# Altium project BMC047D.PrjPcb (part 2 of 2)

## Sheet BMC047D USB.SchDoc
size 431 x 279 mm; Date: Not shown in title block; ApprovedBy: Not shown in title block; CheckedBy: Not shown in title block; Author: Not shown in title block; CompanyName: Not shown in title block; Engineer: Not shown in title block; Organization: Not shown in title block; Address1: Not shown in title block; Address2: Not shown in title block; Address3: Not shown in title block; Address4: Not shown in title block; DocumentNumber: 2; Revision: Use project parameter SCH_Rev; SheetNumber: 2; SheetTotal: 3; PageSetup: Record=PageOptions¦CenterHorizontal=True¦CenterVertical=True¦PrintScale=0.96¦XCorrection=1.00¦YCorrection=1.00¦PrintKind=0¦BorderSize=5000000¦LeftOffset=0¦BottomOffset=0¦Orientation=2¦PaperLength=1000¦PaperWidth=1000¦Scale=100¦PaperSource=15¦PrintQuality=-3¦MediaType=1¦DitherType=10¦PrintScaleMode=1¦PaperKind=Tabloid (11 x 17")¦PaperIndex=17
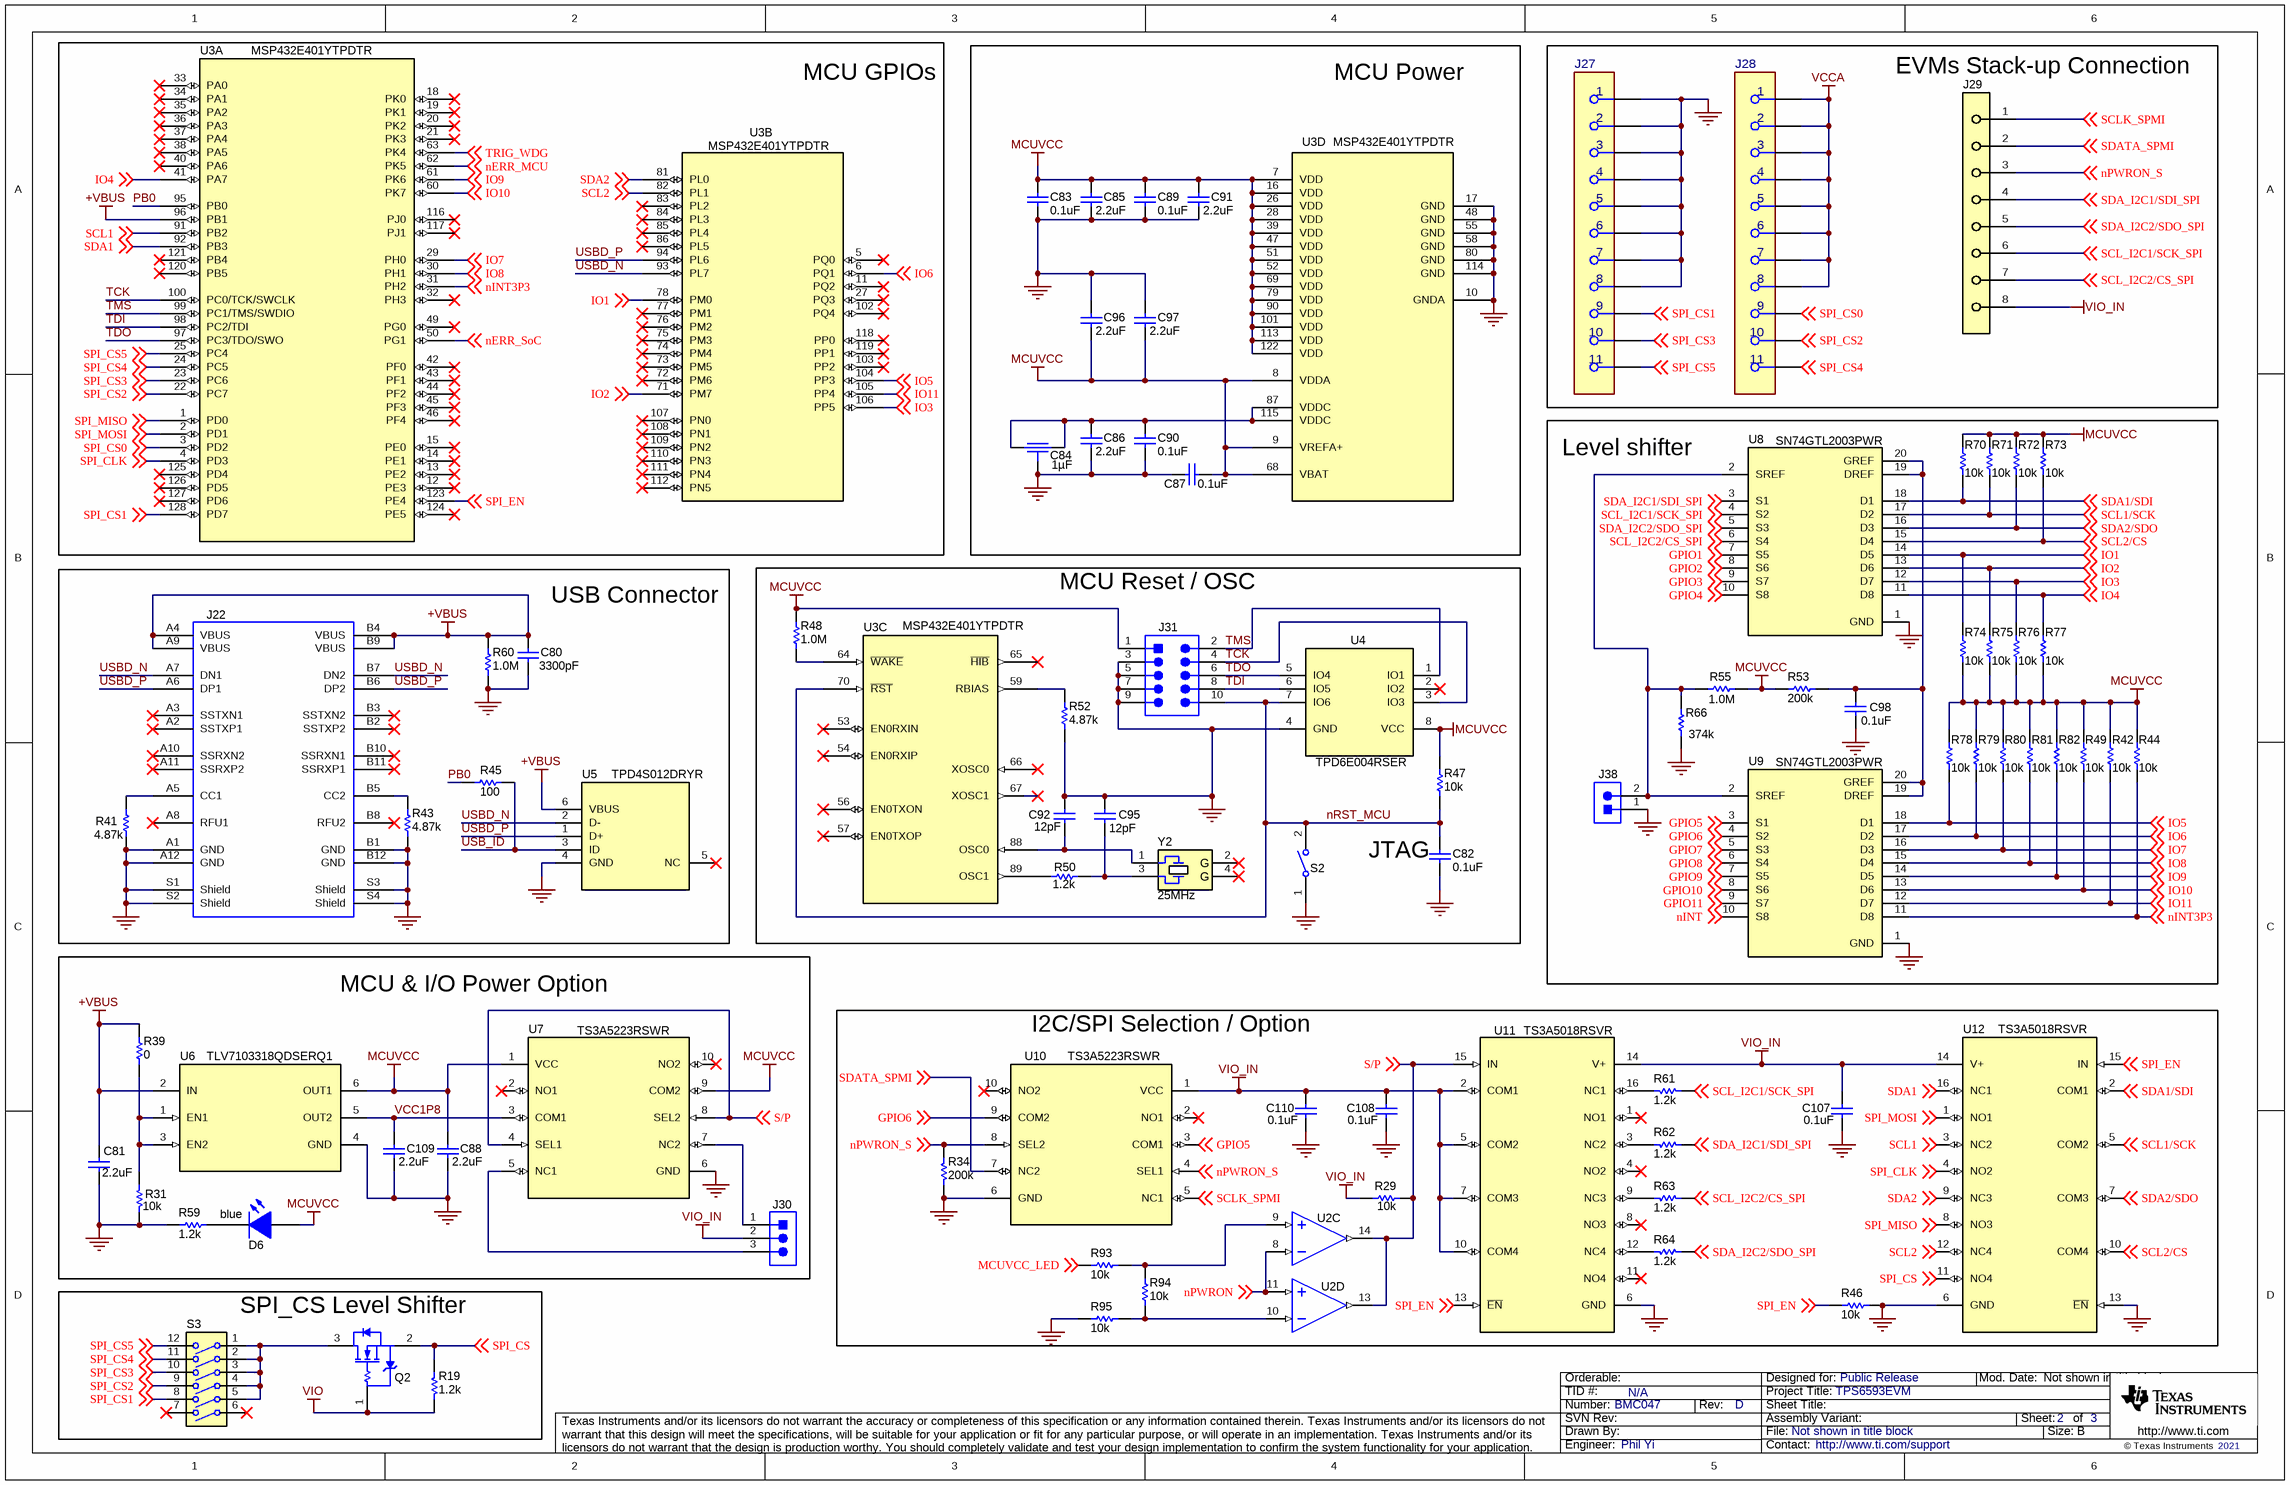
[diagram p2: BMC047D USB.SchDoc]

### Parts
C80  ValueDisplayed: 3300pF  [0603L]  (hidden comment: C0603C332K5RACTU)
C81  ValueDisplayed: 2.2uF  [0603L]  (hidden comment: CGA3E1X7S1C225M080AC)
C82  ValueDisplayed: 0.1uF  [0402L]  (hidden comment: GCM155R71C104KA55D)
C83  ValueDisplayed: 0.1uF  [0402L]  (hidden comment: GCM155R71C104KA55D)
C84  ValueDisplayed: 1µF  [FP-NFM15HC105D0G3_0402-MFG]  (hidden comment: NFM15HC105D0G3)
C85  ValueDisplayed: 2.2uF  [0603L]  (hidden comment: CGA3E1X7S1C225M080AC)
C86  ValueDisplayed: 2.2uF  [0603L]  (hidden comment: CGA3E1X7S1C225M080AC)
C87  ValueDisplayed: 0.1uF  [0402L]  (hidden comment: GCM155R71C104KA55D)
C88  ValueDisplayed: 2.2uF  [0603L]  (hidden comment: CGA3E1X7S1C225M080AC)
C89  ValueDisplayed: 0.1uF  [0402L]  (hidden comment: GCM155R71C104KA55D)
C90  ValueDisplayed: 0.1uF  [0402L]  (hidden comment: GCM155R71C104KA55D)
C91  ValueDisplayed: 2.2uF  [0603L]  (hidden comment: CGA3E1X7S1C225M080AC)
C92  ValueDisplayed: 12pF  [0402L]  (hidden comment: GCM1555C1H120JA16J)
C95  ValueDisplayed: 12pF  [0402L]  (hidden comment: GCM1555C1H120JA16J)
C96  ValueDisplayed: 2.2uF  [0603L]  (hidden comment: CGA3E1X7S1C225M080AC)
C97  ValueDisplayed: 2.2uF  [0603L]  (hidden comment: CGA3E1X7S1C225M080AC)
C98  value 0.1uF  [0402L]  (hidden comment: GCM155R71C104KA55D)
C107  ValueDisplayed: 0.1uF  [0402L]  (hidden comment: GCM155R71C104KA55D)
C108  ValueDisplayed: 0.1uF  [0402L]  (hidden comment: GCM155R71C104KA55D)
C109  ValueDisplayed: 2.2uF  [0603L]  (hidden comment: CGA3E1X7S1C225M080AC)
C110  ValueDisplayed: 0.1uF  [0402L]  (hidden comment: GCM155R71C104KA55D)
D6  Color: blue  [LB Q39G_BLUE]  (hidden comment: LB Q39G-L2N2-35-1)
J22  12401610E4#2A  [Amphenol_12401610E4_2A]  (value not drawn)
J27  ESQ-111-14-T-S  [FP-ESQ-111-14-T-S_HDR11-MFG]  (value not drawn)
J28  ESQ-111-14-T-S  [FP-ESQ-111-14-T-S_HDR11-MFG]  (value not drawn)
J29  ESQ-108-14-T-S  [FP-ESQ-108-14-T-S_HDR8-MFG]  (value not drawn)
J30  61300311121  [WURTH_61300311121]  (value not drawn)
J31  SH-105-01-F-DV-K  [Samtec_FTSH-105-01-x-DV-K]  (value not drawn)
J38  TSW-102-23-T-S  [Samtec_TSW-102-23-X-S]  (value not drawn)
Q2  CSD13381F4  [YJC0003A]  (value not drawn)
R19  ValueDisplayed: 1.2k  [0402L]  (hidden comment: CRCW04021K20JNED)
R29  ValueDisplayed: 10k  [0402L]  (hidden comment: CRCW040210K0JNED)
R31  ValueDisplayed: 10k  [0402L]  (hidden comment: CRCW040210K0JNED)
R34  ValueDisplayed: 200k  [0402]  (hidden comment: CRCW0402200KJNED)
R39  ValueDisplayed: 0  [0402L]  (hidden comment: RK73Z1ETTP)
R41  ValueDisplayed: 4.87k  [0402L]  (hidden comment: CRCW04024K87FKED)
R42  ValueDisplayed: 10k  [0402L]  (hidden comment: CRCW040210K0JNED)
R43  ValueDisplayed: 4.87k  [0402L]  (hidden comment: CRCW04024K87FKED)
R44  ValueDisplayed: 10k  [0402L]  (hidden comment: CRCW040210K0JNED)
R45  ValueDisplayed: 100  [0402L]  (hidden comment: CRCW0402100RJNED)
R46  ValueDisplayed: 10k  [0402L]  (hidden comment: CRCW040210K0JNED)
R47  ValueDisplayed: 10k  [0402L]  (hidden comment: CRCW040210K0JNED)
R48  ValueDisplayed: 1.0M  [0402L]  (hidden comment: CRCW04021M00JNED)
R49  ValueDisplayed: 10k  [0402L]  (hidden comment: CRCW040210K0JNED)
R50  ValueDisplayed: 1.2k  [0402L]  (hidden comment: CRCW04021K20JNED)
R52  ValueDisplayed: 4.87k  [0402L]  (hidden comment: CRCW04024K87FKED)
R53  ValueDisplayed: 200k  [0402L]  (hidden comment: CRCW0402200KJNED)
R55  ValueDisplayed: 1.0M  [0402L]  (hidden comment: CRCW04021M00JNED)
R59  ValueDisplayed: 1.2k  [0402L]  (hidden comment: CRCW04021K20JNED)
R60  ValueDisplayed: 1.0M  [0402L]  (hidden comment: CRCW04021M00JNED)
R61  ValueDisplayed: 1.2k  [0402L]  (hidden comment: CRCW04021K20JNED)
R62  ValueDisplayed: 1.2k  [0402L]  (hidden comment: CRCW04021K20JNED)
R63  ValueDisplayed: 1.2k  [0402L]  (hidden comment: CRCW04021K20JNED)
R64  ValueDisplayed: 1.2k  [0402L]  (hidden comment: CRCW04021K20JNED)
R66  ValueDisplayed: 374k  [0402L]  (hidden comment: CRCW0402374KFKED)
R70  ValueDisplayed: 10k  [0402L]  (hidden comment: CRCW040210K0JNED)
R71  ValueDisplayed: 10k  [0402L]  (hidden comment: CRCW040210K0JNED)
R72  ValueDisplayed: 10k  [0402L]  (hidden comment: CRCW040210K0JNED)
R73  ValueDisplayed: 10k  [0402L]  (hidden comment: CRCW040210K0JNED)
R74  ValueDisplayed: 10k  [0402L]  (hidden comment: CRCW040210K0JNED)
R75  ValueDisplayed: 10k  [0402L]  (hidden comment: CRCW040210K0JNED)
R76  ValueDisplayed: 10k  [0402L]  (hidden comment: CRCW040210K0JNED)
R77  ValueDisplayed: 10k  [0402L]  (hidden comment: CRCW040210K0JNED)
R78  ValueDisplayed: 10k  [0402L]  (hidden comment: CRCW040210K0JNED)
R79  ValueDisplayed: 10k  [0402L]  (hidden comment: CRCW040210K0JNED)
R80  ValueDisplayed: 10k  [0402L]  (hidden comment: CRCW040210K0JNED)
R81  ValueDisplayed: 10k  [0402L]  (hidden comment: CRCW040210K0JNED)
R82  ValueDisplayed: 10k  [0402L]  (hidden comment: CRCW040210K0JNED)
R93  ValueDisplayed: 10k  [0402L]  (hidden comment: CRCW040210K0JNED)
R94  ValueDisplayed: 10k  [0402L]  (hidden comment: CRCW040210K0JNED)
R95  ValueDisplayed: 10k  [0402L]  (hidden comment: CRCW040210K0JNED)
S2  147873-1  [SW_147873-1]  (value not drawn)
S3  218-6LPST  [SW_218-6LPST]  (value not drawn)
U2  LM2901AVQPWRQ1  [PW0014A_N]  (value not drawn)  (parts C,D of 5)
U3  MSP432E401YTPDTR  [PDT0128A]  (parts A,B,C,D of 4)
U4  TPD6E004RSER  [RSE0008A]
U5  TPD4S012DRYR  [DRY0006A]
U6  TLV7103318QDSERQ1  [DSE0006A]
U7  TS3A5223RSWR  [RSW0010A]
U8  SN74GTL2003PWR  [PW0020A_N]
U9  SN74GTL2003PWR  [PW0020A_N]
U10  TS3A5223RSWR  [RSW0010A]
U11  TS3A5018RSVR  [RSV0016A]
U12  TS3A5018RSVR  [RSV0016A]
Y2  Frequency_Fixed: 25MHz  [NDK_NX3225GA]  (hidden comment: NX3225GA-25.000M-STD-CRG-2)

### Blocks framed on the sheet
MCU GPIOs: U3
MCU Power: C83-C87 C89-C91 C96 C97 U3
EVMs Stack-up Connection: J27-J29
Level shifter: C98 J38 R42 R44 R49 R53 R55 R66 R70-R82 U8 U9
USB Connector: C80 J22 R41 R43 R45 R60 U5
MCU & I/O Power Option: C81 C88 C109 D6 J30 R31 R39 R59 U6 U7
I2C/SPI Selection / Option: C107 C108 C110 R29 R34 R46 R61-R64 R93-R95 U2 U10-U12
SPI_CS Level Shifter: Q2 R19 S3

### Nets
+VBUS: C80.1 C81.1 J22.A4(VBUS) J22.A9(VBUS) J22.B4(VBUS) J22.B9(VBUS) R39.1 R60.1 U3.96(PB1) U5.6(VBUS) U6.2(IN)
GND: C80.2 C81.2 C82.2 C83.2 C84.2 C85.2 C86.2 C87.1 C88.2 C89.2 C90.2 C91.2 C92.2 C95.2 C96.1 C97.1 C98.2 C107.1 C108.1 C109.2 C110.1 J22.A1(GND) J22.A12(GND) J22.B1(GND) J22.B12(GND) J22.S1(Shield) J22.S2(Shield) J22.S3(Shield) J22.S4(Shield) J27.1 J27.2 J27.3 J27.4 J27.5 J27.6 J27.7 J27.8 J31.3 J31.5 J31.7 J31.9 J38.1 R31.1 R34.1 R41.2 R43.2 R46.1 R52.2 R59.2 R60.2 R66.1 R95.2 S2.1 U3.10(GNDA) U3.17(GND) U3.48(GND) U3.55(GND) U3.58(GND) U3.80(GND) U3.114(GND) U4.4(GND) U5.4(GND) U6.4(GND) U7.6(GND) U8.1(GND) U9.1(GND) U10.6(GND) U11.6(GND) U12.6(GND) U12.13(~{EN})
MCUVCC: C83.1 C85.1 C87.2 C88.1 C89.1 C91.1 C96.2 C97.2 D6.1(A) J31.1 R42.1 R44.1 R47.2 R48.2 R49.1 R53.1 R55.2 R70.1 R71.1 R72.1 R73.1 R74.2 R75.2 R76.2 R77.2 R78.1 R79.1 R80.1 R81.1 R82.1 U3.7(VDD) U3.8(VDDA) U3.9(VREFA+) U3.16(VDD) U3.26(VDD) U3.28(VDD) U3.39(VDD) U3.47(VDD) U3.51(VDD) U3.52(VDD) U3.68(VBAT) U3.69(VDD) U3.79(VDD) U3.90(VDD) U3.101(VDD) U3.113(VDD) U3.122(VDD) U4.8(VCC) U6.6(OUT1) U7.1(VCC) U7.9(COM2)
VCCA: J28.1 J28.2 J28.3 J28.4 J28.5 J28.6 J28.7 J28.8
VIO: Q2.1(G) R19.1
VIO_IN: C107.2 C108.2 C110.2 J29.8 J30.2 R29.1 U10.1(VCC) U11.2(COM1) U11.5(COM2) U11.7(COM3) U11.10(COM4) U11.14(V+) U12.14(V+)
GPIO1: U8.7(S5) ; off-sheet GPIO1
GPIO2: U8.8(S6) ; off-sheet GPIO2
GPIO3: U8.9(S7) ; off-sheet GPIO3
GPIO4: U8.10(S8) ; off-sheet GPIO4
GPIO5: U9.3(S1) U10.3(COM1) ; off-sheet GPIO5
GPIO6: U9.4(S2) U10.9(COM2) ; off-sheet GPIO6
GPIO7: U9.5(S3) ; off-sheet GPIO7
GPIO8: U9.6(S4) ; off-sheet GPIO8
GPIO9: U9.7(S5) ; off-sheet GPIO9
GPIO10: U9.8(S6) ; off-sheet GPIO10
GPIO11: U9.9(S7) ; off-sheet GPIO11
IO1: R74.1 U3.78(PM0) U8.14(D5) ; off-sheet IO1
IO2: R75.1 U3.71(PM7) U8.13(D6) ; off-sheet IO2
IO3: R76.1 U3.106(PP5) U8.12(D7) ; off-sheet IO3
IO4: R77.1 U3.41(PA7) U8.11(D8) ; off-sheet IO4
IO5: R78.2 U3.104(PP3) U9.18(D1) ; off-sheet IO5
IO6: R79.2 U3.6(PQ1) U9.17(D2) ; off-sheet IO6
IO7: R80.2 U3.29(PH0) U9.16(D3) ; off-sheet IO7
IO8: R81.2 U3.30(PH1) U9.15(D4) ; off-sheet IO8
IO9: R82.2 U3.61(PK6) U9.14(D5) ; off-sheet IO9
IO10: R49.2 U3.60(PK7) U9.13(D6) ; off-sheet IO10
IO11: R42.2 U3.105(PP4) U9.12(D7) ; off-sheet IO11
MCUVCC_LED: R93.1 ; off-sheet MCUVCC_LED
nERR_MCU: U3.62(PK5) ; off-sheet nERR_MCU
nERR_SoC: U3.50(PG1) ; off-sheet nERR_SoC
nINT: U9.10(S8) ; off-sheet nINT
nINT3P3: R44.2 U3.31(PH2) U9.11(D8) ; off-sheet nINT3P3
nPWRON: U2.8(-IN3) U2.11(+IN4) ; off-sheet nPWRON
nPWRON_S: J29.3 R34.2 U10.4(SEL1) U10.8(SEL2) ; off-sheet nPWRON_S
nRST_MCU: C82.1 J31.10 R47.1 S2.2 U3.70(~{RST}) U4.7(IO6)
PB0: R45.1 U3.95(PB0)
S/P: R29.2 U2.13(OUT4) U2.14(OUT3) U7.4(SEL1) U7.8(SEL2) U11.15(IN) ; off-sheet S/P
SCL1: U3.91(PB2) U12.3(NC2) ; off-sheet SCL1
SCL1/SCK: R71.2 U8.17(D2) U12.5(COM2) ; off-sheet SCL1/SCK
SCL2: U3.82(PL1) U12.12(NC4) ; off-sheet SCL2
SCL2/CS: R73.2 U8.15(D4) U12.10(COM4) ; off-sheet SCL2/CS
SCL_I2C1/SCK_SPI: J29.6 R61.2 U8.4(S2) ; off-sheet SCL_I2C1/SCK_SPI
SCL_I2C2/CS_SPI: J29.7 R63.2 U8.6(S4) ; off-sheet SCL_I2C2/CS_SPI
SCLK_SPMI: J29.1 U10.5(NC1) ; off-sheet SCLK_SPMI
SDA1: U3.92(PB3) U12.16(NC1) ; off-sheet SDA1
SDA1/SDI: R70.2 U8.18(D1) U12.2(COM1) ; off-sheet SDA1/SDI
SDA2: U3.81(PL0) U12.9(NC3) ; off-sheet SDA2
SDA2/SDO: R72.2 U8.16(D3) U12.7(COM3) ; off-sheet SDA2/SDO
SDA_I2C1/SDI_SPI: J29.4 R62.2 U8.3(S1) ; off-sheet SDA_I2C1/SDI_SPI
SDA_I2C2/SDO_SPI: J29.5 R64.2 U8.5(S3) ; off-sheet SDA_I2C2/SDO_SPI
SDATA_SPMI: J29.2 U10.7(NC2) ; off-sheet SDATA_SPMI
SPI_CLK: U3.4(PD3) U12.4(NO2) ; off-sheet SPI_CLK
SPI_CS: Q2.2(S) R19.2 U12.11(NO4) ; off-sheet SPI_CS
SPI_CS0: J28.9 U3.3(PD2) ; off-sheet SPI_CS0
SPI_CS1: J27.9 S3.8(5A) U3.128(PD7) ; off-sheet SPI_CS1
SPI_CS2: J28.10 S3.9(4A) U3.22(PC7) ; off-sheet SPI_CS2
SPI_CS3: J27.10 S3.10(3A) U3.23(PC6) ; off-sheet SPI_CS3
SPI_CS4: J28.11 S3.11(2A) U3.24(PC5) ; off-sheet SPI_CS4
SPI_CS5: J27.11 S3.12(1A) U3.25(PC4) ; off-sheet SPI_CS5
SPI_EN: R46.2 U3.123(PE4) U11.13(~{EN}) U12.15(IN) ; off-sheet SPI_EN
SPI_MISO: U3.1(PD0) U12.8(NO3) ; off-sheet SPI_MISO
SPI_MOSI: U3.2(PD1) U12.1(NO1) ; off-sheet SPI_MOSI
TCK: J31.4 U3.100(PC0/TCK/SWCLK) U4.3(IO3)
TDI: J31.8 U3.98(PC2/TDI) U4.6(IO5)
TDO: J31.6 U3.97(PC3/TDO/SWO) U4.5(IO4)
TMS: J31.2 U3.99(PC1/TMS/SWDIO) U4.1(IO1)
TRIG_WDG: U3.63(PK4) ; off-sheet TRIG_WDG
USB_ID: R45.2 U5.3(ID)
USBD_N: J22.A7(DN1) J22.B7(DN2) U3.93(PL7) U5.2(D-)
USBD_P: J22.A6(DP1) J22.B6(DP2) U3.94(PL6) U5.1(D+)
VCC1P8: C109.1 U6.5(OUT2) U7.3(COM1)
NetC84_1: C84.1 C84.3 C86.1 C90.1 U3.87(VDDC) U3.115(VDDC)
NetC92_1: C92.1 U3.88(OSC0) Y2.1
NetC95_1: C95.1 R50.2 Y2.3
NetC98_1: C98.1 R53.2 U8.19(DREF) U8.20(GREF) U9.19(DREF) U9.20(GREF)
NetD6_2: D6.2(K) R59.1
NetJ22_A5: J22.A5(CC1) R41.1
NetJ22_B5: J22.B5(CC2) R43.1
NetJ30_1: J30.1 U7.7(NC2)
NetJ30_3: J30.3 U7.5(NC1)
NetJ38_2: J38.2 R55.1 R66.2 U8.2(SREF) U9.2(SREF)
NetQ2_3: Q2.3(D) S3.1 S3.2 S3.3 S3.4 S3.5
NetR31_2: R31.2 R39.2 U6.1(EN1) U6.3(EN2)
NetR48_1: R48.1 U3.64(~{WAKE})
NetR50_1: R50.1 U3.89(OSC1)
NetR52_1: R52.1 U3.59(RBIAS)
NetR61_1: R61.1 U11.16(NC1)
NetR62_1: R62.1 U11.3(NC2)
NetR63_1: R63.1 U11.9(NC3)
NetR64_1: R64.1 U11.12(NC4)
NetR93_2: R93.2 R94.2 U2.9(+IN3)
NetR94_1: R94.1 R95.1 U2.10(-IN4)

Not connected (* = marked no-connect by the designer): J22 A2(SSTXP1)* A3(SSTXN1)* A8(RFU1)* A10(SSRXN2)* A11(SSRXP2)* B2(SSTXP2)* B3(SSTXN2)* B8(RFU2)* B10(SSRXN1)* B11(SSRXP1)*; S3 6* 7(6A)*; U3 5(PQ0)* 11(PQ2)* 12(PE3)* 13(PE2)* 14(PE1)* 15(PE0)* 18(PK0)* 19(PK1)* 20(PK2)* 21(PK3)* 27(PQ3)* 32(PH3)* 33(PA0)* 34(PA1)* 35(PA2)* 36(PA3)* 37(PA4)* 38(PA5)* 40(PA6)* 42(PF0)* 43(PF1)* 44(PF2)* 45(PF3)* 46(PF4)* 49(PG0)* 53(EN0RXIN)* 54(EN0RXIP)* 56(EN0TXON)* 57(EN0TXOP)* 65(~{HIB})* 66(XOSC0)* 67(XOSC1)* 72(PM6)* 73(PM5)* 74(PM4)* 75(PM3)* 76(PM2)* 77(PM1)* 83(PL2)* 84(PL3)* 85(PL4)* 86(PL5)* 102(PQ4)* 103(PP2)* 107(PN0)* 108(PN1)* 109(PN2)* 110(PN3)* 111(PN4)* 112(PN5)* 116(PJ0)* 117(PJ1)* 118(PP0)* 119(PP1)* 120(PB5)* 121(PB4)* 124(PE5)* 125(PD4)* 126(PD5)* 127(PD6)*; U4 2(IO2)*; U5 5(NC)*; U7 2(NO1)* 10(NO2)*; U10 2(NO1)* 10(NO2)*; U11 1(NO1)* 4(NO2)* 8(NO3)* 11(NO4)*; Y2 2(GND)* 4(GND)*

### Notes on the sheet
- MCU Reset / OSC
- (near C82) JTAG

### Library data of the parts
C80 = CMP-0006922-4: CAP, CERM, 3300 pF, 50 V, +/- 10%, X7R, 0603; Manufacturer: Kemet; TaMin_C: -55°C; Polarized: N; SizeAreaWB_mm2: 4.68; Value1: Unknown; U/M: EA; Value: 3300pF; TaMax_C: 125°C; SizeZ_mm: 1; SizeX_mm: 1.6; SizeY_mm: 0.8; Cap_Case: 0603; Value2: 50V; SizeArea_mm2: 1.28; Cap_F: 3.3nF; AEC Category: Q200
C81 = CMP-0007068-4: CAP, CERM, 2.2 uF, 16 V, +/- 20%, X7S, AEC-Q200 Grade 1, 0603; Manufacturer: TDK; SizeAreaWB_mm2: 4.68; Cap_F: 2.2µF; Value1: Unknown; Value2: 16V; Value: 2.2uF; AEC Grade: 1; SizeX_mm: 1.6; TaMin_C: -55°C; AEC Category: Q200; U/M: EA; TaMax_C: 125°C; SizeArea_mm2: 1.28; Polarized: N; SizeY_mm: 0.8; Cap_Case: 0603; AEC Qualified: Y
C82 C83 C87 C89 C90 C107 C108 C110 = CMP-0006351-2: CAP, CERM, 0.1 uF, 16 V, +/- 10%, X7R, 0402; Manufacturer: MuRata; TaMin_C: -55°C; Polarized: N; SizeAreaWB_mm2: 3; Value1: Unknown; U/M: EA; Value: 0.1uF; TaMax_C: 125°C; SizeZ_mm: 0.6; SizeX_mm: 1; SizeY_mm: 0.5; Cap_Case: 0402; Value2: 16V; Cap_F: 100nF; AEC Category: Q200
C84 = CMP-0086486-3: 3 Terminals Chip Multilayer Ceramic Capacitor (EMIFIL); Manufacturer: Murata; Tolerance_%: 20%; SizeZ_mm: 0.5mm; AEC Qualified: No; VDC_V: 4V
C85 C86 C88 C91 C96 C97 C109 = CMP-0007068-4: CAP, CERM, 2.2 uF, 16 V, +/- 20%, X7S, AEC-Q200 Grade 1, 0603; Manufacturer: TDK; TaMin_C: -55°C; Polarized: N; SizeAreaWB_mm2: 4.68; Value1: Unknown; U/M: EA; Value: 2.2uF; TaMax_C: 125°C; SizeZ_mm: 1; SizeX_mm: 1.6; SizeY_mm: 0.8; Cap_Case: 0603; Value2: 16V; SizeArea_mm2: 1.28; AEC Qualified: Y; Cap_F: 2.2µF; AEC Category: Q200
C92 C95 = CMP-0085816-1: CAP, CERM, 12 pF, 50 V,+/- 5%, C0G/NP0, AEC-Q200 Grade 1, 0402; Manufacturer: MuRata; TaMin_C: -55°C; Polarized: N; SizeAreaWB_mm2: 3; U/M: EA; Value: 12pF; TaMax_C: 125°C; SizeZ_mm: 0.6; SizeX_mm: 1; SizeY_mm: 0.5; Cap_Case: 0402; Value2: 50V; AEC Qualified: Y; AEC Category: Q200
C98 = CMP-0006351-2: CAP, CERM, 0.1 uF, 16 V, +/- 10%, X7R, 0402; Manufacturer: MuRata; TaMin_C: -55°C; Polarized: N; SizeAreaWB_mm2: 3; Value1: Unknown; U/M: EA; TaMax_C: 125°C; SizeZ_mm: 0.6; SizeX_mm: 1; SizeY_mm: 0.5; Cap_Case: 0402; Value2: 16V; Cap_F: 100nF; AEC Category: Q200
D6 = CMP-0002849-2: LED, Blue, SMD; Manufacturer: OSRAM; Tjmax_C: 95°C; Value1: W; Io_A: 150mA; Vf_V: 2.85V
J22 = CMP-0075218-1: Receptacle, 0.5mm, USB TYPE C, R/A, SMT; Manufacturer: Amphenol Canada; CNHeader: False; Current_A: 5A; Green_Lifecycle: Not Set; Gender: Female; Green_REACh: Incomplete; Row_Count: 2; Pitch_mm: 0.5; ContactFinish: Tin; CT: True; Cert_UL: Y
J27 J28 = CMP-0094103-1: Conn Elevated Socket SKT 11 POS 2.54mm Solder ST Thru-Hole Tube; Manufacturer: Samtec; SizeZ_mm: 11.3mm; Conn Gender: Female; ContactFinish: Tin,Nickel; Conn Orientation: Vertical; Row_Count: 1; AEC Qualified: No; Is Female: yes
J29 = CMP-0087040-2: Board-To-Board Connector, Vertical, ESQ Series, 8 Contacts, Receptacle, 2.54 mm, Through Hole; Manufacturer: Samtec; Voltage_V: 550V; Current_A: 5.7A; ContactFinish: Tin,Nickel; Row_Count: 1
J30 = CMP-0054796-4: Header, 2.54 mm, 3x1, Gold, TH; Manufacturer: Wurth Elektronik; Green_Lifecycle: Active; Green_REACh: Passed; CT: FALSE; CNHeader: TRUE
J31 = CMP-0075670-2: Header (Shrouded), 1.27mm, 5x2, Gold, SMT; PartNumber: FTSH-105-01-F-DV-K; Manufacturer: Samtec; Pitch_mm: 1.27; Gender: Male; Cert_CSA: Y; Current_A: 3.3A; Row_Count: 2
J38 = CMP-0084558-1: Header, 2.54mm, 2x1, Tin, TH; Manufacturer: Samtec; Cert_UL: Y; Row_Count: 1; Pitch_mm: 2.54; Gender: Male; Current_A: 6.3A; Voltage_V: 550V; Shrouded: N
Q2 = CMP-0000197-1: MOSFET, N-CH, 12 V, 2.1 A, YJC0003A (PICOSTAR-3); Alternate Manufacturer: None; Manufacturer: Texas Instruments; SizeZ_mm: 0.35; ChType: N; Value2: 1.06 nC; Value1: 0.1; VdsMax_V: 12V; SizeX_mm: 1.035; SizeY_mm: 0.635; Vgs_V: 8V; Value: 12V; Rdson45_ohm: 0.14; SizeArea_mm2: 0.657225; AEC Category: Q101; IdsMax_A: 2.1A; SizeAreaWB_mm2: 3.327225; U/M: EA; QgTyp_nC: 1.06
R19 R50 R59 R61-R64 = CMP-0026854-5: RES, 1.2 k, 5%, 0.063 W, AEC-Q200 Grade 0, 0402; Manufacturer: Vishay-Dale; Power_W: 63mW; TempCo: 200 ppm/C; Value_Code: 1k20; Value: 1.2k; EIA_Code: E24; SizeX_mm: 1; SizeY_mm: 0.5; SizeZ_mm: 0.6; Value2: 0.063W; AEC Qualified: Y; VDC_V: 50V; AEC Category: Q200; AEC Grade: 0
R29 R31 R42 R44 R46 R47 R49 R70-R82 R93-R95 = CMP-0026825-5: RES, 10 k, 5%, 0.063 W, AEC-Q200 Grade 0, 0402; Manufacturer: Vishay-Dale; Power_W: 63mW; TempCo: 200 ppm/C; Value_Code: 10k0; Value: 10k; EIA_Code: E24; SizeX_mm: 1; SizeY_mm: 0.5; SizeZ_mm: 0.6; Value2: 0.063W; AEC Qualified: Y; VDC_V: 50V; AEC Category: Q200; AEC Grade: 0
R34 R53 = CMP-0026873-2: RES, 200 k, 5%, 0.063 W, AEC-Q200 Grade 0, 0402; Manufacturer: Vishay-Dale; Power_W: 63mW; TempCo: 200 ppm/C; Value: 200k; EIA_Code: E24; SizeX_mm: 1; SizeY_mm: 0.5; SizeZ_mm: 0.6; Value2: 0.063W; AEC Qualified: Y; VDC_V: 50V; AEC Category: Q200; AEC Grade: 0
R39 = CMP-0027007-2: RES, 0, 5%, 0.063 W, AEC-Q200 Grade 0, 0402; Manufacturer: KOA Speer; Power_W: 63mW; TempCo: ppm/C; Value_Code: 0000; U/M: EA; Value: 0; EIA_Code: E24; SizeX_mm: 1; SizeY_mm: 0.5; SizeZ_mm: 0.6; Value2: 0.063W; AEC Qualified: Y; AEC Category: Q200
R41 R43 R52 = CMP-0026413-2: RES, 4.87 k, 1%, 0.063 W, AEC-Q200 Grade 0, 0402; Manufacturer: Vishay-Dale; Power_W: 63mW; TempCo: 100 ppm/C; Value_Code: 4k87; Value: 4.87k; EIA_Code: E96; SizeX_mm: 1; SizeY_mm: 0.5; SizeZ_mm: 0.6; Value2: 0.063W; AEC Qualified: Y; VDC_V: 50V; AEC Category: Q200; AEC Grade: 0
R45 = CMP-0026824-3: RES, 100, 5%, 0.063 W, AEC-Q200 Grade 0, 0402; Manufacturer: Vishay-Dale; Power_W: 63mW; TempCo: 200 ppm/C; Value_Code: 100R; Value: 100; EIA_Code: E24; SizeX_mm: 1; SizeY_mm: 0.5; SizeZ_mm: 0.6; Value2: 0.063W; AEC Qualified: Y; VDC_V: 50V; AEC Category: Q200; AEC Grade: 0
R48 R55 R60 = CMP-0026859-2: RES, 1.0 M, 5%, 0.063 W, AEC-Q200 Grade 0, 0402; Manufacturer: Vishay-Dale; Power_W: 63mW; TempCo: 200 ppm/C; Value_Code: 1M00; Value: 1.0Meg; EIA_Code: E24; Res_ohm: 1M; SizeX_mm: 1; SizeY_mm: 0.5; SizeZ_mm: 0.6; Value2: 0.063W; AEC Qualified: Y; VDC_V: 50V; AEC Category: Q200; AEC Grade: 0
R66 = CMP-0026317-2: RES, 374 k, 1%, 0.063 W, AEC-Q200 Grade 0, 0402; Manufacturer: Vishay-Dale; Power_W: 63mW; TempCo: 100 ppm/C; Value: 374k; EIA_Code: E96; SizeX_mm: 1; SizeY_mm: 0.5; SizeZ_mm: 0.6; Value2: 0.063W; AEC Qualified: Y; VDC_V: 50V; AEC Category: Q200; AEC Grade: 0
S2 = CMP-0002216-1: Switch, SPST, Off-On,  50 mA,24V, SMD; Manufacturer: TE Connectivity; CurrentRating_mA: 50A; PositionCount: 1
S3 = CMP-0002304-1: Switch, SPST, Slide, Off-On, 6 Pos, 0.025A, 24V, SMD; Manufacturer: CTS Electrocomponents; CurrentRating_mA: 25A; PositionCount: 6; SizeX_mm: 8.44; SizeY_mm: 8.79; SizeZ_mm: 2.65; SizeArea_mm2: 74.1876; SizeAreaWB_mm2: 112.6476
U2 = CMP-0065405-2: AEC-Q100 Quad Comparator, PW0014A (TSSOP-14); Manufacturer: Texas Instruments; CompType: IC; SizeY_mm: 5.0; SizeAreaWB_mm2: 58.8; Rating: Automotive; SizeZ_mm: 1.2; AEC Category: Q200; AEC Qualified: Y; SizeArea_mm2: 32.0; SizeX_mm: 6.4
U3 = CMP-0077954-1: MSP432E401YTPDT, PDT0128A (TQFP-128); Alternate Manufacturer: Texas Instruments; SizeAreaWB_mm2: 324; SizeZ_mm: 1.2; SizeX_mm: 16; SizeArea_mm2: 256; CompType: IC; AEC Qualified: N; AEC Category: Q200
U4 = CMP-0043125-4: Low-Capacitance 6-Channel +/-15 kV ESD Protection Array for High-Speed Data Interfaces, RSE0008A (UQFN-8); Manufacturer: Texas Instruments; IO Leakage Current(nA): 1; IO Capacitance(Typ)(pF): 1.6; 1394 / Firewire: TRUE; Eco-Plan: Green (RoHS & no Sb/Br); SubFamily: ESD Solution; Breakdown Voltage(Min)(V): 6; IEC 61000-4-2 Air-Gap(+/- kV): 12; IEC 61000-4-2 Contact(+/- kV): 8; AEC Category: Q200; AEC Qualified: N; CompType: IC; SizeAreaWB_mm2: 6.25; SizeArea_mm2: 2.25; SizeX_mm: 1.5; SizeZ_mm: 0.6
U5 = CMP-0043122-3: 4-Channel USB ESD Solution with Power Clamp, DRY0006A (USON-6); Manufacturer: Texas Instruments; IO Leakage Current(nA): 10; USB High Speed: TRUE; Eco-Plan: Green (RoHS & no Sb/Br); Breakdown Voltage(Min)(V): 6; IO Capacitance(Typ)(pF): 0.8; AEC Category: Q200; AEC Qualified: N; CompType: IC; SizeAreaWB_mm2: 4.9; SizeArea_mm2: 1.45; SizeX_mm: 1.0; SizeZ_mm: 0.6; Rating: Catalog
U6 = CMP-0073729-1: Automotive Catalog, Dual, 200mA, Low-IQ Low-Dropout Regulator for Portable Devices, DSE0006A (WSON-6); Alternate Manufacturer: Texas Instruments; SizeAreaWB_mm2: 6.25; U/M: EA; SizeZ_mm: 0.8; SizeX_mm: 1.5; SizeArea_mm2: 2.25; CompType: IC
U7 U10 = CMP-0085520-1: 0.5Ω Dual SPDT Bidirectional Analog Switch, RSW0010A (UQFN-10); Manufacturer: Texas Instruments; Rating: Catalog; SizeY_mm: 1.8; AEC Qualified: N; SizeZ_mm: 0.55; CompType: IC; SizeArea_mm2: 2.52; AEC Category: Q200; SizeAreaWB_mm2: 6.72; SizeX_mm: 1.4
U8 U9 = CMP-0066429-1: 8-BIT BIDIRECTIONAL LOW-VOLTAGE TRANSLATOR, PW0020A (TSSOP-20); Alternate Manufacturer: Texas Instruments; SizeAreaWB_mm2: 73.96; U/M: EA; SizeZ_mm: 1.2; SizeX_mm: 6.6; SizeArea_mm2: 43.56; CompType: IC
U11 U12 = CMP-0067415-1: 10-Ohm Quad SPDT Analog Switch, RSV0016A (UQFN-16); Alternate Manufacturer: Texas Instruments; SizeAreaWB_mm2: 10.08; U/M: EA; SizeZ_mm: 0.55; SizeX_mm: 1.8; SizeY_mm: 2.6; SizeArea_mm2: 4.68; CompType: IC
Y2 = CMP-0004652-3: Crystal, 25 MHz, 8pF, SMD; Manufacturer: NDK; TaMax_C: 85°C; TaMin_C: -40°C; Frequency Stability: +/-30ppm

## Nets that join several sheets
+VBUS: BMC047D Main (6 pins), BMC047D USB (11 pins)
GND: BMC047D Main (140 pins), BMC047D USB (70 pins)
MCUVCC: BMC047D Main (J7.1), BMC047D USB (51 pins)
VCCA: BMC047D Main (25 pins), BMC047D USB (8 pins)
VIO_IN: BMC047D Main (11 pins), BMC047D USB (13 pins)
GPIO1: BMC047D Main (J9.1 J11.1 J15.11 U1.32), BMC047D USB (U8.7)
GPIO2: BMC047D Main (J7.4 J9.2 J11.2 U1.33), BMC047D USB (U8.8)
GPIO3: BMC047D Main (J7.7 J9.3 J11.3 U1.46), BMC047D USB (U8.9)
GPIO4: BMC047D Main (J9.4 J11.4 U1.47), BMC047D USB (U8.10)
GPIO5: BMC047D Main (J9.5 J11.5), BMC047D USB (U9.3 U10.3)
GPIO6: BMC047D Main (J9.6 J11.6), BMC047D USB (U9.4 U10.9)
GPIO7: BMC047D Main (J7.9 J9.7 J11.7 U1.18), BMC047D USB (U9.5)
GPIO8: BMC047D Main (J9.8 J11.8 R51.1), BMC047D USB (U9.6)
GPIO9: BMC047D Main (J9.9 J11.9 R54.1), BMC047D USB (U9.7)
GPIO10: BMC047D Main (J9.10 J11.10 R32.1), BMC047D USB (U9.8)
GPIO11: BMC047D Main (J7.11 J9.11 J11.11 U1.53), BMC047D USB (U9.9)
MCUVCC_LED: BMC047D Main (R22.2 R23.2 R24.2 U2.3), BMC047D USB (R93.1)
nERR_MCU: BMC047D Main (J7.8), BMC047D USB (U3.62)
nERR_SoC: BMC047D Main (J7.6), BMC047D USB (U3.50)
nINT: BMC047D Main (J15.1 R35.1 U1.14), BMC047D USB (U9.10)
nPWRON: BMC047D Main (J15.4 J37.1 S1.2 U1.20), BMC047D USB (U2.8 U2.11)
nPWRON_S: BMC047D Main (J37.2), BMC047D USB (J29.3 R34.2 U10.4 U10.8)
SCL_I2C1/SCK_SPI: BMC047D Main (U1.31), BMC047D USB (J29.6 R61.2 U8.4)
SCL_I2C2/CS_SPI: BMC047D Main (J15.10), BMC047D USB (J29.7 R63.2 U8.6)
SCLK_SPMI: BMC047D Main (U1.23), BMC047D USB (J29.1 U10.5)
SDA_I2C1/SDI_SPI: BMC047D Main (U1.30), BMC047D USB (J29.4 R62.2 U8.3)
SDA_I2C2/SDO_SPI: BMC047D Main (J7.5), BMC047D USB (J29.5 R64.2 U8.5)
SDATA_SPMI: BMC047D Main (U1.24), BMC047D USB (J29.2 U10.7)
SPI_EN: BMC047D Main (J7.2), BMC047D USB (R46.2 U3.123 U11.13 U12.15)
TRIG_WDG: BMC047D Main (J7.3 J7.10), BMC047D USB (U3.63)

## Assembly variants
001: not fitted C1 C3 C16 C17 C79 C94 FID1 FID2 FID3 FID4 FID5 FID6 J31 J32 J33 J34 J35 J36 J39 J40 J41 J42 J43 J44 R3 R4 R5 R6 R7 R25 TP9 TP10 TP11 TP12 TP13
002: not fitted C1 C3 C16 C17 C79 C94 FID1 FID2 FID3 FID4 FID5 FID6 J25 J31 J32 J33 J34 J35 J36 J39 J40 J41 J42 J43 J44 R3 R4 R5 R6 R25 TP9 TP10 TP11 TP12 TP13
003: not fitted C1 C3 C16 C17 C79 C94 FID1 FID2 FID3 FID4 FID5 FID6 J24 J25 J31 J32 J33 J34 J35 J36 J39 J40 J41 J42 J43 J44 R3 R4 R6 R25 TP9 TP10 TP11 TP12 TP13
004: not fitted C1 C3 C16 C17 C79 C94 FID1 FID2 FID3 FID4 FID5 FID6 J23 J24 J25 J31 J32 J33 J34 J35 J36 J39 J40 J41 J42 J43 J44 R2 R4 R6 R25 TP9 TP10 TP11 TP12 TP13
005: not fitted C1 C3 C16 C17 C79 C94 FID1 FID2 FID3 FID4 FID5 FID6 J24 J31 J32 J33 J34 J35 J36 J39 J40 J41 J42 J43 J44 R3 R4 R7 R25 TP9 TP10 TP11 TP12 TP13
006: not fitted C1 C3 C16 C17 C79 C94 D1 FID1 FID2 FID3 FID4 FID5 FID6 J23 J24 J25 J31 J32 J33 J34 J35 J36 J39 J40 J41 J42 J43 J44 Q1 R2 R4 R6 R20 R21 R26 TP9 TP10 TP11 TP12 TP13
